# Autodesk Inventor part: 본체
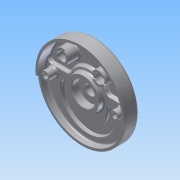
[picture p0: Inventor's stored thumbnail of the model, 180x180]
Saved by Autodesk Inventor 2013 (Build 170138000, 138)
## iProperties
Created: 2015-05
Part Number: 본체
Material: 알루미늄 6061
Document SubType Name: Modeling
Designer: Administrator
Density: 2.71 g/cm^3
Mass: 1042.94 g
Surface Area: 1023.38 cm^2
Volume: 384.847 cm^3
Author: Administrator
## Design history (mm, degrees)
sketch "스케치1"
  geometry: C1 r 95 at (0, 0); 1 further point
  constraints: 1 centre point, 1 coincident
  dimensions: "d0" = 190 diameter of C1
extrude "돌출1" new body sketch "스케치1" distance "d2" = 32; taper "d3" = 0 deg
sketch "스케치3"
  geometry: L1 (-101, 52)-(108, 52); L2 (-94.239, 12)-(94.239, 12); C1 r 15 at (-40, 52); C2 r 15 at (40, 52); A1 r 95 centre (0, 0) between (-94.239, 12) and (94.239, 12) reference; A2 r 90 centre (0, 0) between (-89.196, 12) and (89.196, 12); A3 r 42 centre (0, 0) between (40.249, 12) and (-40.249, 12)
  constraints: 6 point on circle, 6 point on line, 4 centre point, 4 end point, 2 coincident, 1 equal radius, 1 horizontal, 1 parallel
  dimensions: "d7" = 180 diameter of A2; "d9" = 52 distance from line of A1.centre L1; "d10" = 84 diameter of A3; "d11" = 12 distance from line of A1.centre L2; "d20" = 30 diameter of C1; "d22" = 40 horizontal distance of C1.centre A1.centre; "d23" = 40 horizontal distance of C2.centre A1.centre
extrude "돌출3" cut sketch "스케치3" distance "d14" = 25; taper "d15" = 0 deg
extrude "돌출4" cut sketch "스케치3" distance "d18" = 18; taper "d19" = 0 deg
sketch "스케치5"
  geometry: C1 r 15 at (-40, 52); C2 r 15 at (40, 52); A1 r 42 centre (0, 0) between (40.249, 12) and (-40.249, 12) reference
  constraints: 2 centre point, 1 equal radius, 1 horizontal alignment
  dimensions: "d24" = 30 diameter of C1; "d26" = 40 horizontal distance of A1.centre C1.centre; "d27" = 40 horizontal distance of C2.centre A1.centre; "d28" = 52 vertical distance of A1.centre C2.centre
extrude "돌출5" join sketch "스케치5" stored distance "d29" = 8; taper "d30" = 0 deg
sketch "스케치6"
  geometry: C1 r 95 at (0, 0) reference
hole "구멍1" diameter "d33" = 20; stored, may be unused: countersink angle "d37" = 90 deg, drill point angle "d39" = 0 deg; dims "d31" = 10, "d32" = 10, "d34" = 6, "d35" = 4, "d36" = 2, "d38" = 8
hole "구멍2" diameter "d42" = 20; stored, may be unused: countersink angle "d46" = 90 deg, drill point angle "d48" = 0 deg; dims "d40" = 10, "d41" = 10, "d43" = 6, "d44" = 4, "d45" = 2, "d47" = 8
sketch "스케치7"
  geometry: L1 (-6, 13.748)-(-6, -13.748); L2 (6, 13.748)-(6, -13.748); C1 r 10 at (0, 0) reference; A1 r 15 centre (0, 0) between (-6, 13.748) and (-6, -13.748) reference; 1 further point
  constraints: 4 end point, 4 point on circle, 1 parallel, 1 vertical
  dimensions: "d49" = 6 distance from line of C1.centre L1; "d50" = 6 distance from line of L2 C1.centre
extrude "돌출7" cut sketch "스케치7" distance "d53" = 3; taper "d54" = 0 deg
sketch "스케치8"
  geometry: L1 (-13.748, 6)-(13.748, 6); L2 (-13.748, -6)-(13.748, -6); C1 r 10 at (0, 0) reference; A1 r 15 centre (0, 0) between (-13.748, 6) and (13.748, 6) reference; 1 further point
  constraints: 4 end point, 4 point on circle, 1 horizontal, 1 parallel
  dimensions: "d55" = 6 distance from line of L1 C1.centre; "d56" = 6 distance from line of L2 C1.centre
extrude "돌출8" cut sketch "스케치8" distance "d57" = 3; taper "d58" = 0 deg
sketch "스케치9"
  geometry: C1 r 35 at (0, 0); A1 r 90 centre (0, 0) between (-89.196, 12) and (89.196, 12) reference
  constraints: 1 centre point, 1 coincident
  dimensions: "d59" = 70 diameter of C1
extrude "돌출9" join sketch "스케치9" distance "d61" = 10; taper "d62" = -10 deg
sketch "스케치17"
  geometry: C1 r 95 at (0, 0) reference; C2 r 26 at (0, 0)
  constraints: 1 centre point, 1 coincident
  dimensions: "d156" = 52 diameter of C2
extrude "돌출17" join sketch "스케치17" distance "d158" = 12; taper "d159" = -15 deg
hole "구멍3" diameter "d65" = 23; stored, may be unused: countersink angle "d69" = 90 deg, drill point angle "d71" = 0 deg; dims "d63" = 10, "d64" = 10, "d66" = 6, "d67" = 50, "d68" = 15, "d70" = 8
sketch "스케치13"
  geometry: L1 (-89.658, -7.844)-(-94.638, -8.28); L2 (89.658, -7.844)-(94.638, -8.28); L3 (-123, 0)-(146, 0); A1 r 90 centre (0, 0) between (-89.658, -7.844) and (89.658, -7.844) reference; A2 r 95 centre (0, 0) between (94.638, -8.28) and (-94.638, -8.28) reference
  constraints: 6 end point, 4 point on circle, 1 horizontal, 1 point on line
  dimensions: "d113" = 170 deg angle of L2 L1; "d114" = 5 deg angle of L1 L3
sketch "스케치10"
  geometry: C1 r 35 at (0, 0) reference; C2 r 9 at (-74, 0); C3 r 9 at (74, 0)
  constraints: 2 centre point, 2 horizontal alignment, 1 equal radius
  dimensions: "d72" = 18 diameter of C2; "d74" = 74 distance of C2.centre C1.centre; "d75" = 74 distance of C3.centre C1.centre
extrude "돌출10" join sketch "스케치10" stored distance "d76" = 10; taper "d77" = 0 deg
hole "구멍4" diameter "d80" = 11; stored, may be unused: countersink angle "d84" = 90 deg, drill point angle "d86" = 0 deg; dims "d78" = 10, "d79" = 10, "d81" = 6, "d82" = 18, "d83" = 11, "d85" = 8
hole "구멍5" diameter "d89" = 11; stored, may be unused: countersink angle "d93" = 90 deg, drill point angle "d95" = 0 deg; dims "d87" = 10, "d88" = 10, "d90" = 6, "d91" = 18, "d92" = 11, "d94" = 8
sketch "스케치11"
  geometry: L1 (40.249, 12)-(89.196, 12) reference; L2 (-69.854, -19)-(69.854, -19); C1 r 35 at (0, 0) reference; A1 r 59 centre (0, -19) between (-58.704, -13.1) and (58.704, -13.1); A2 r 41 centre (0, -19) between (-40.794, -14.9) and (40.794, -14.9); A3 r 9 centre (-49.749, -14) between (-40.794, -14.9) and (-58.704, -13.1); A4 r 50 centre (0, -19) between (-49.749, -14) and (49.749, -14); A5 r 9 centre (49.749, -14) between (58.704, -13.1) and (40.794, -14.9); 1 further point
  constraints: 10 point on circle, 5 centre point, 4 coincident, 2 end point, 2 tangent, 1 midpoint, 1 parallel, 1 vertical alignment
  dimensions: "d96" = 19 distance from line of L2 C1.centre; "d97" = 59 radius of A1; "d98" = 41 radius of A2; "d100" = 5 distance from line of L2 A3.centre; "d101" = 18 diameter of A3; "d102" = 9 radial gap between concentric circles of A2 A4; "d103" = 18 diameter of A5; "d104" = 5 distance from line of L2 A5.centre
extrude "돌출12" cut sketch "스케치11" distance "d107" = 7; taper "d108" = 0 deg
extrude "돌출14" cut sketch "스케치13" distance "d117" = 5; taper "d118" = 0 deg
fillet "모깎기2" dims "d136" = 5
fillet "모깎기3" dims "d137" = 0.3
fillet "모깎기5" dims "d139" = 1
fillet "모깎기6" dims "d140" = 10
fillet "모깎기9" dims "d143" = 3
fillet "모깎기12" dims "d146" = 3
chamfer "모따기1" distance "d147" = 1; stored, may be unused: second distance "d148" = 2, angle "d149" = 45 deg
fillet "모깎기13" dims "d150" = 3
fillet "모깎기14" dims "d151" = 3
node "솔리드1"
other parameters: "d109" = 170 deg, "d130" = 136
